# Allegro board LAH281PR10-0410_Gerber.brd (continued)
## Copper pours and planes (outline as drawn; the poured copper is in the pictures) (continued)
LX_IO on TOP (solid shape): 305.96,62.68 305.96,60.42 307.81,58.58 309.83,58.58 309.9,58.5 309.9,58.37 309.82,58.3 308.65,58.3 308.65,58.29 307.5,58.29 307.37,58.16 307.37,56.29 306.2,55.13 306.2,53.84 305.99,53.63 304.54,53.63 304.39,53.77 304.39,62.23 304.87,62.71 305.93,62.71
MODE_IO on TOP (solid shape): 307.62,61.65 307.62,59.98 308.42,59.18 309.01,59.18 309.07,59.12 309.07,58.8 309.04,58.78 307.88,58.78 306.74,59.91 306.74,61.62 306.86,61.74 307.53,61.74
Net_461 on BOTTOM (solid shape): 147.69,141.3 137.69,141.3 137.69,156.3 147.69,156.3
Net_961 on BOTTOM (solid shape): outline of 196 points within 276.35,88.09 280.85,92.59
Net_962 on BOTTOM (solid shape): outline of 193 points within 261.35,88.09 265.85,92.55
Net_963 on BOTTOM (solid shape): outline of 191 points within 246.35,88.09 250.85,92.54
Net_964 on BOTTOM (solid shape): outline of 196 points within 231.35,88.09 235.85,92.59
PGOOD_5V on BOTTOM (solid shape): 55.42,7.21 55.45,7.21 55.92,6.75 56.31,6.75 56.42,6.64 56.42,5.36 56.3,5.24 55.89,5.24 55.62,5.51 55.62,6.46 55.03,7.05 54.16,7.05 54.12,7.09 54.12,7.28 54.17,7.33 55.3,7.33
REG_OUT on BOTTOM (solid shape): 14.53,22.54 14.53,20.97 15.81,19.69 15.81,18.69 15.74,18.62 15.01,18.62 12.67,20.96 12.67,22.72 12.93,22.98 14.09,22.98
RING2 on TOP (solid shape): 388.31,23.13 388.31,22.75 388.06,22.49 386.41,22.49 386.26,22.65 385.29,22.65 385.24,22.7 384.38,22.7 384.33,22.75 384.33,22.9 384.35,22.93 385.34,22.93 385.42,22.85 386.08,22.85 386.48,23.26 388.19,23.26
RING2 on BOTTOM (solid shape): 390.78,18.35 390.88,18.35 391.01,18.23 391.01,17.46 390.93,17.39 390.48,17.39 390.4,17.47 390.34,17.47 390.19,17.62 389.41,17.62 389.15,17.87 389.15,18.63 389.51,18.99 390.14,18.99
RING2 on IN1 (solid shape): 389.15,23 389.15,22.34 389.07,22.27 388.26,22.27 387.91,22.62 387.55,22.62 387.5,22.57 387.27,22.57 387.04,22.8 387.04,23.31 387.17,23.43 388.72,23.43
RING2 on IN1 (solid shape): 390.21,19.79 390.16,19.57 390.24,19.38 390.24,18.89 390.42,18.71 390.42,18.25 390.34,18.18 389.18,18.18 388.74,18.61 388.74,19.85 388.87,19.98 390.01,19.98
RING2_R on TOP (solid shape): 394.89,18.67 394.89,18.19 394.74,18.04 393.16,18.04 392.81,17.68 392.81,17.35 392.94,17.22 392.94,17.02 392.39,16.47 391.97,16.47 391.96,16.48 391.91,16.48 391.63,16.76 391.59,16.82 391.54,16.86 390.97,17.43 390.97,17.86 391.23,18.12 391.71,18.12 392.95,19.36 394.21,19.36
RING2_R on BOTTOM (solid shape): 392.94,17.86 392.94,16.96 392.49,16.51 392.1,16.51 391.26,17.35 391.26,17.93 391.32,18 392.8,18
RING2_R on IN1 (solid shape): 395.67,19.89 395.67,19 395.29,18.62 393.13,18.62 392.87,18.87 392.87,19.33 393.81,20.27 395.29,20.27
S3_OVP on BOTTOM (solid shape): 38.97,15.63 38.97,15.46 39.05,15.31 39.29,15.15 39.57,15.21 39.7,15.22 39.77,15.11 39.77,14.52 39.73,14.52 39.73,13.68 39.58,13.52 37.28,13.52 37.06,13.3 37.06,12.89 36.95,12.79 36.24,12.79 36.13,12.9 36.13,13.79 35.75,14.16 35.75,15.38 36,15.63 37.25,15.63 37.25,15.63
S3_OVP on IN1 (solid shape): outline of 457 points within 31.99,9.5 40.26,17.1
S5_OVP on BOTTOM (solid shape): 44.06,15.56 44.78,15.56 45.4,14.95 45.89,14.95 45.97,14.87 45.97,12.92 45.7,12.64 44.4,12.64 44.34,12.71 44.34,13.5 44.1,13.73 42.97,13.73 42.84,13.86 42.84,14.37 43.51,15.03 43.51,15.49 43.19,15.81 41.76,15.81 41.64,15.92 41.64,16.17 41.73,16.26 43.37,16.26
SA_SW on TOP (solid shape): 283.61,68.77 283.61,64.99 283.82,64.78 285.04,64.78 285.09,64.73 285.09,63.97 284.85,63.73 281.16,63.73 279.58,65.32 279.58,66.13 279.65,66.21 280.54,66.21 280.57,66.23 280.57,67.02 280.54,67.05 279.65,67.05 279.6,67.1 279.6,68.6 279.8,68.79 282.73,68.79 282.86,68.93 283.46,68.93
SDVDD1 on TOP (solid shape): 32.14,26.07 32.14,25.14 31.96,24.96 31.88,24.9 31.82,24.83 31.52,24.52 30.76,24.52 30.59,24.7 30.59,25.9 31,26.3 31.9,26.3
SDVDD1 on BOTTOM (solid shape): 17.42,13.37 17.42,11.85 17.59,11.68 17.59,11.01 17.45,10.87 17.2,10.87 17.04,11.03 17.04,11.81 17.16,11.93 17.16,13.33 17.27,13.43 17.36,13.43
SDVDD1 on BOTTOM (solid shape): 31.69,26.85 31.69,24.64 31.56,24.5 31.41,24.5 31.4,24.51 31.28,24.52 31.15,24.51 31.14,24.5 30.77,24.5 30.55,24.72 30.56,24.76 30.55,24.95 30.45,25.11 30.45,26.41 30.6,26.62 30.57,26.87 30.55,26.91 30.66,27.02 31.52,27.02
SDVDD1 on IN4: outline of 81 points within 16.91,10.72 32.86,25.31
SDVDD2 on TOP (solid shape): 13.22,26.96 13.22,25.61 11.93,24.32 10.41,24.32 10.08,24.65 10.08,25.69 10.51,26.12 11.57,26.12 12.1,26.65 12.1,26.81 12.12,26.95 12.11,27.09 12.29,27.26 12.92,27.26
SDVDD2 on BOTTOM (solid shape): 13.52,26.99 13.52,24.38 13.58,24.32 13.58,23.74 13.48,23.64 12.58,23.64 12.31,23.9 12.31,25.58 11.74,26.15 11.74,26.91 11.93,27.09 13.42,27.09
SDVDD2 on BOTTOM (solid shape): 17,13.38 17,11.97 16.91,11.87 16.91,11.16 16.79,11.04 16.44,11.04 16.42,11.06 16.42,11.56 16.41,11.64 16.37,11.71 16.36,11.72 16.35,11.79 16.35,11.93 16.79,12.36 16.79,13.39 16.84,13.44 16.94,13.44
SDVDD2 on IN2 (solid shape): 13.64,23.96 13.65,23.9 13.66,23.86 13.66,22.92 13.26,22.52 12.79,22.52 12.35,22.96 12.35,24.09 12.57,24.31 13.29,24.31
SDVDD2 on IN2 (solid shape): 17.15,12.26 17.15,12.02 17.11,12 16.92,11.72 17.04,11.41 17.06,11.37 17.05,11.32 16.97,11.15 16.99,10.97 17.01,10.93 16.88,10.8 15.95,10.8 15.85,10.85 15.83,10.97 15.79,11.26 15.54,11.43 15.49,11.44 15.49,12.06 15.86,12.43 16.98,12.43
SLEEVE on TOP (solid shape): 386.41,23.72 386.41,23.48 385.93,23 385.49,23 385.42,23.08 384.38,23.08 384.33,23.13 384.33,23.31 384.35,23.33 385.37,23.33 385.47,23.43 385.62,23.43 386.05,23.87 386.26,23.87
SLEEVE on BOTTOM (solid shape): 389.96,16.25 390.84,16.25 390.93,16.15 390.93,15.59 390.83,15.48 388.21,15.48 388.14,15.56 388.14,16.13 388.63,16.63 389.58,16.63
SLEEVE on IN2 (solid shape): 389.71,16.86 389.71,15.74 389.56,15.59 388.21,15.59 388.16,15.64 388.16,16.55 388.85,17.24 389.33,17.24
SLEEVE on IN2 (solid shape): 387.02,24.09 387.02,23.41 386.53,22.93 385.47,22.93 385.26,23.13 385.26,23.76 385.65,24.14 385.8,24.14 385.93,24.27 386.84,24.27
SLEEVE_R on TOP (solid shape): 391.92,16.27 392.19,16.27 392.69,15.76 394.33,15.76 394.52,15.57 394.52,15.15 394.24,14.87 391.53,14.87 390.52,15.88 390.52,16.82 390.62,16.93 390.62,17 390.73,17.1 391.09,17.1
SLEEVE_R on BOTTOM (solid shape): 392,16.39 392.76,16.39 392.9,16.25 392.9,15.69 392.8,15.59 391.23,15.59 391.12,15.7 391.12,16.14 390.56,16.7 390.56,16.86 390.62,16.93 390.62,17.06 390.71,17.15 391.23,17.15
SLEEVE_R on IN1 (solid shape): 395.81,16.14 395.81,15.38 395.64,15.21 395.09,15.3 395.12,14.75 393.65,14.75 393.39,15 393.39,16.14 393.65,16.4 395.55,16.4
SNUB_1.2V on TOP (solid shape): 132.61,8.3 133.02,8.3 133.3,8.01 133.3,6.25 132.97,5.93 131.58,5.93 131.28,6.23 131.28,8.34 131.51,8.57 132.33,8.57
SNUB_1V on TOP (solid shape): 111.06,40.08 111.85,40.08 112.04,39.89 112.04,38.8 111.81,38.57 110.05,38.57 109.94,38.68 109.9,38.76 109.84,38.83 109.55,38.94 109.28,38.77 109.07,38.98 109.07,40.25 109.17,40.35 110.79,40.35
SNUB_CHG on TOP (solid shape): 97.31,3.17 97.31,1.57 97.07,1.33 95.35,1.33 95.12,1.55 95.12,3.19 95.32,3.38 97.1,3.38
SNUB_IO on TOP (solid shape): 303.35,62.7 303.35,61.08 303.22,60.95 302.23,60.95 301.9,61.28 301.19,61.28 301.14,61.33 301.14,62.32 301.57,62.75 303.3,62.75
SUNB_3VR on TOP (solid shape): 330.38,11.95 331.29,11.95 331.54,11.7 331.54,10.68 331.16,10.3 329.51,10.3 329.26,10.56 329.26,11.95 329.38,12.08 330.25,12.08
UG_1.2V on TOP (solid shape): 124.99,3.34 124.99,1.38 124.74,1.13 123.91,1.13 123.64,1.4 123.64,3.16 123.92,3.44 124.88,3.44
UG_1.2V on TOP (solid shape): 116.25,12.84 116.25,12.18 116.15,12.08 115.49,12.08 115.39,12.18 115.39,12.51 115.24,12.66 114.32,12.66 114.27,12.71 114.27,12.87 114.35,12.94 115.64,12.94 115.75,13.05 116.05,13.05
UG_1.2V on IN1 (solid shape): 117.45,12.59 117.45,11.85 117.42,11.83 115.77,11.83 115.42,12.18 115.42,12.54 115.9,13.02 117.02,13.02
UG_1.2V on IN1 (solid shape): 125.6,3.04 125.6,1.22 125.36,0.97 122.72,0.97 122.65,1.05 122.86,1.39 122.62,1.71 122.57,1.76 122.55,1.77 122.55,3.02 122.86,3.32 125.32,3.32
UG_+1VSP on TOP (solid shape): 102.13,42.88 102.13,41.84 102,41.71 99.99,41.71 99.78,41.92 99.78,42.97 99.87,43.06 101.95,43.06
UG_+1VSP on TOP (solid shape): 106.27,32.59 106.27,32.44 106.3,32.41 106.3,32.4 106.46,32.24 106.52,32.16 106.6,32.1 106.86,31.85 106.86,30.87 106.77,30.79 106.49,30.79 106.43,30.86 106.43,30.94 106.43,31.49 106.39,31.65 106.26,31.74 106.25,31.75 105.74,32.25 105.74,32.56 105.82,32.64 106.22,32.64
UG_+1VSP on IN3 (solid shape): 101.23,43.13 101.23,41.66 101.06,41.5 100.27,41.5 100.01,41.75 100.01,43.08 100.11,43.18 101.17,43.18
UG_+1VSP on IN3 (solid shape): 106.3,32.63 106.3,32.36 106.71,31.95 106.71,31.85 106.58,31.71 105.73,31.71 105.14,32.3 105.14,33.01 105.23,33.1 105.83,33.1
UGATE_CHG on TOP (solid shape): 94.38,10.67 94.38,9.81 94.2,9.64 93,9.64 92.69,9.95 92.69,10.78 92.86,10.95 93.07,10.95 93.09,10.96 94.08,10.96
N17828613 on TOP (solid shape): 51.14,28.35 51.88,28.35 52.31,27.92 52.31,27.05 52.16,26.9 50.73,26.9 50.57,26.74 50.57,26.02 50.49,25.95 49.91,25.95 49.81,26.05 49.81,27.02 49.16,27.67 47.43,27.67 47.08,28.01 47.08,28.49 47.3,28.71 49.84,28.71 50.07,28.94 50.55,28.94
N17829900 on TOP (solid shape): 51.26,32.19 51.26,31.41 51.48,31.19 51.59,30.98 51.79,30.88 51.9,30.77 51.9,29.52 51.7,29.32 51.1,29.32 50.64,29.78 50.64,30.75 49.81,31.58 49.81,32.22 49.92,32.34 51.12,32.34
N17880182 on TOP (solid shape): 58.24,29.33 58.24,28.63 58.27,28.61 58.27,28.44 58.6,28.11 60.44,28.11 60.5,27.94 60.64,27.83 60.68,27.82 60.68,26.56 60.32,26.2 58.65,26.2 58.61,26.21 57.35,27.47 57.35,27.5 57.33,27.53 57.33,27.73 57.25,27.8 57.07,27.8 56.94,27.93 56.94,28.54 56.82,28.67 56.18,28.67 56.1,28.74 56.1,29.34 56.08,29.37 56.08,29.38 56.26,29.56 58.01,29.56
N20816750 on TOP (solid shape): 292.56,16.76 292.56,16.07 292.29,15.81 291.09,15.81 291.08,15.82 290.91,15.87 290.74,15.82 290.73,15.82 290.67,15.82 290.6,15.74 289.76,15.74 289.68,15.82 289.68,15.99 289.81,16.12 290.4,16.12 290.6,16.32 291.07,16.32 291.69,16.94 292.38,16.94
N20816752 on TOP (solid shape): 292.56,18.14 292.56,17.29 292.4,17.13 291.58,17.13 291.13,16.68 290.32,16.68 290.26,16.69 289.85,16.69 289.82,16.69 289.77,16.68 289.66,16.8 289.66,16.98 289.79,17.11 290.93,17.11 291.56,17.74 291.56,18.13 291.7,18.26 292.44,18.26
N20816821 on TOP (solid shape): 290.21,69.93 290.21,69.08 290.05,68.92 289.31,68.92 289.16,68.77 289.16,68.47 288.66,67.96 287.78,67.96 287.72,68.03 287.72,68.24 287.82,68.33 288.59,68.33 288.86,68.6 288.86,69.61 289.27,70.03 290.12,70.03
N20816822 on TOP (solid shape): 290.25,68.6 290.25,67.85 290.06,67.66 289.35,67.66 288.78,67.09 288.74,67.09 288.62,67.09 288.47,66.94 287.8,66.94 287.7,67.03 287.7,67.27 287.82,67.38 287.89,67.37 287.92,67.36 288.33,67.36 288.41,67.38 288.48,67.41 288.5,67.42 288.54,67.42 289.35,68.24 289.35,68.63 289.45,68.73 290.12,68.73
N24451540 on TOP (solid shape): 55.98,29.25 55.98,28.67 55.75,28.44 55.58,28.44 55.56,28.42 55.51,28.42 55.27,28.19 54.81,28.19 54.52,27.91 54.52,27.88 54.52,27.86 54.49,27.72 54.52,27.58 54.52,27.57 54.52,27.54 54.74,27.32 55.32,27.32 55.57,27.57 57.1,27.57 57.22,27.45 57.22,26.94 57.1,26.81 54.66,26.81 54.57,26.85 54.54,26.94 54.45,27.18 54.22,27.3 54.14,27.35 54.11,27.43 54.11,28.06 54.15,28.15 54.25,28.18 54.55,28.31 54.62,28.63 54.65,28.73 54.75,28.78 54.93,28.78 55.16,29.02 55.16,29.21 55.22,29.26 55.96,29.26
N24455122 on TOP (solid shape): 55.95,31 55.95,29.64 55.94,29.63 55.22,29.63 54.94,29.35 54.94,29.1 54.81,28.97 54.43,28.97 54.3,29.1 54.3,30.62 54.56,30.88 54.94,30.88 55.19,31.13 55.83,31.13
N24481164 on BOTTOM (solid shape): 71.17,28.35 71.17,27.33 71.02,27.19 70.35,27.19 70.24,27.08 69.73,27.08 69.56,27.25 69.56,28.48 69.59,28.52 71,28.52
N24501583 on TOP (solid shape): 80,17.91 80.04,17.91 80.21,17.91 80.25,17.91 80.29,17.92 80.46,17.92 80.59,17.79 80.59,16.91 80.34,16.65 79.83,16.65 79.58,16.91 79.58,17.16 79.45,17.29 78.69,17.29 78.56,17.41 78.56,17.79 78.69,17.92 79.96,17.92
N24501661 on TOP (solid shape): 83.89,21.1 83.89,19.83 83.77,19.7 81.1,19.7 80.97,19.83 80.97,20.49 81.02,20.5 81.23,20.67 81.27,20.94 81.29,21.05 81.39,21.1 82.95,21.1
N24501681 on TOP (solid shape): 84.02,19.32 84.02,18.48 83.51,17.97 83.14,17.97 83.09,18.02 83.09,18.03 82.8,18.23 82.48,18.09 82.46,18.06 82.44,18.05 81.48,18.05 81.23,18.3 81.23,19.32 81.35,19.45 83.89,19.45
N24501694 on TOP (solid shape): 89.81,27.36 89.81,25.94 88.51,24.64 88.51,24.28 88.21,23.97 88.21,23.25 87.8,22.84 86.94,22.84 86.69,23.09 86.69,24.19 87.07,24.57 87.07,24.98 87.59,25.5 87.59,25.95 88.15,26.51 88.15,27 88.64,27.49 89.68,27.49
N24501736 on TOP (solid shape): 90.3,22.83 91.42,22.83 91.65,22.6 91.65,21.4 91.46,21.21 90.68,21.21 90.24,21.65 88.86,21.65 88.67,21.85 88.67,22.51 89.15,22.99 90.15,22.99
N24501930 on TOP (solid shape): 84.78,20.54 84.91,20.41 84.91,20.21 85.16,19.95 85.16,19.57 85.04,19.45 84.15,19.45 84.02,19.57 84.02,20.35 84.02,20.97 84.15,21.1 84.78,21.1
N24501932 on TOP (solid shape): 84.91,22.87 84.91,22.37 85.16,22.11 85.54,22.11 85.8,21.86 85.8,20.46 85.67,20.33 85.16,20.33 84.96,20.54 84.96,21.37 84.86,21.47 84.29,21.47 84.2,21.55 84.2,22.16 84.4,22.37 84.4,22.87 84.52,22.99 84.79,22.99
N24565509 on BOTTOM (solid shape): 41.73,19.94 41.73,19.45 41.85,19.33 41.9,19.27 41.95,19.22 42.24,18.94 42.24,18.25 42.43,18.07 44.01,18.07 44.43,18.49 44.43,19.06 44.62,19.25 46.55,19.25 46.82,18.98 46.82,18.52 46.68,18.38 45.32,18.38 44.86,17.92 44.86,16.6 44.7,16.45 44.12,16.45 43.49,17.08 41.68,17.08 41.2,17.56 41.2,19.59 41.2,19.6 41.22,19.73 41.2,19.85 41.19,19.89 41.33,20.03 41.65,20.03
N24565597 on BOTTOM (solid shape): 42.8,22.97 42.8,22.3 42.41,21.91 42.41,21.36 42.33,21.28 42.02,21.28 41.88,21.41 41.88,21.78 41.73,21.94 41.7,21.96 41.25,22.42 41.25,22.82 41.34,22.91 41.91,22.91 42.05,23.05 42.72,23.05
N24623814 on BOTTOM (solid shape): 37.79,19.88 37.79,19.09 37.91,18.98 37.91,18.35 37.17,17.62 37.17,17.17 37.38,16.96 38.82,16.96 38.97,16.82 38.97,16.57 38.85,16.45 35.95,16.45 35.27,17.13 34.54,17.13 34.44,17.23 34.44,17.67 34.56,17.79 34.69,17.79 34.7,17.79 34.99,17.79 35.06,17.87 35.26,17.87 35.27,17.86 35.43,17.86 36.02,18.46 36.02,19.8 36.12,19.9 36.64,19.9 36.78,20.03 37.64,20.03
N24623894 on BOTTOM (solid shape): 38.76,23.18 38.76,22.49 38.43,22.17 38.43,21.96 38.42,21.94 38.42,21.42 38.28,21.28 38.08,21.28 37.94,21.42 37.94,21.84 37.79,21.99 37.83,22.03 37.87,22.48 37.45,22.61 37.33,22.62 37.27,22.73 37.27,23.31 37.35,23.38 38.55,23.38
N25196480 on TOP (solid shape): 357.58,47.26 357.58,46.37 357.5,46.3 356.07,46.3 356.07,46.31 355.23,46.31 355.04,46.5 355.04,47 355.42,47.39 357.45,47.39
N26820574 on TOP (solid shape): 79.24,27.82 79.47,27.73 79.71,27.82 80.61,27.82 80.72,27.7 80.72,27.7 80.97,27.45 80.97,26.05 80.08,25.16 80.08,24.27 78.81,24.27 78.43,24.65 78.43,26.41 78.74,26.71 78.74,27.11 78.58,27.27 78.58,27.67 78.73,27.82
N26822393 on TOP (solid shape): 76.21,24.67 76.21,24.08 76.35,24.08 76.35,22.67 76.15,22.47 75.49,22.47 75.33,22.62 75.33,24.6 75.49,24.75 76.12,24.75
N42077965 on TOP (solid shape): 292.36,60.18 292.36,59.22 292.14,59 291.51,59 291.43,58.92 291.37,58.92 291.37,58.86 290.44,57.93 289.61,57.93 289.55,57.98 289.55,58.23 289.67,58.35 290.38,58.35 290.4,58.36 290.65,58.61 290.65,58.62 291.24,59.21 291.24,60.1 291.44,60.31 292.22,60.31
N42077969 on TOP (solid shape): 292.24,58.74 292.24,57.93 292.16,57.85 291.37,57.85 290.87,57.34 290.84,57.34 290.63,57.24 290.52,57.02 290.52,57 290.43,56.91 290.21,56.91 290.15,56.92 289.75,56.92 289.69,56.91 289.66,56.91 289.57,57 289.57,57.26 289.63,57.33 290.16,57.33 290.2,57.36 290.21,57.36 290.39,57.48 290.43,57.7 290.42,57.73 290.54,57.85 290.54,57.85 291.53,58.84 292.14,58.84
N42078041 on TOP (solid shape): 292.45,49.08 292.45,48.18 292.25,47.97 291.43,47.97 290.69,47.23 289.73,47.23 289.69,47.28 289.69,47.51 289.76,47.59 290.45,47.59 290.47,47.61 290.64,47.61 291.58,48.56 291.58,48.96 291.75,49.12 292.41,49.12
N42078055 on TOP (solid shape): 292.51,47.66 292.51,46.97 292.22,46.68 291.18,46.68 290.72,46.22 290.69,46.19 290.66,46.17 289.85,46.17 289.79,46.17 289.77,46.17 289.66,46.27 289.69,46.29 289.69,46.53 289.78,46.62 289.85,46.61 290.26,46.61 290.32,46.62 290.38,46.64 290.4,46.65 290.46,46.65 291.58,47.77 292.4,47.77
N50626329 on BOTTOM (solid shape): 43.47,32.37 43.47,31 42.86,30.39 42.82,30.39 42.82,30.35 42.75,30.29 42.75,29.76 42.65,29.66 42.4,29.66 42.35,29.6 41.23,29.6 41.09,29.73 41.09,30.37 42.07,31.34 42.07,31.92 42.7,32.55 43.29,32.55
N51087711 on TOP (solid shape): 323.8,2.43 323.8,1.67 323.67,1.54 323.16,1.54 323.15,1.54 323.07,1.55 323,1.54 322.99,1.54 322.27,1.54 322.19,1.63 322.32,1.76 322.32,2.55 323.67,2.55
N51093717 on BOTTOM (solid shape): 51.98,7.29 51.98,6.75 50.36,5.13 50.36,4.18 50.19,4 49.26,4 48.63,4.64 48.63,5.29 50.7,7.36 51.91,7.36
N51093813 on TOP (solid shape): 135.5,111.29 135.5,110.52 135.42,110.44 134.88,110.44 134.4,109.95 134.4,109.52 134.4,109.51 134.4,108.91 134.29,108.81 132.57,108.81 132.4,108.98 132.4,110.85 132.51,110.96 134.67,110.96 134.78,111.07 134.78,111.31 134.85,111.38 135.41,111.38
N61688512 on TOP (solid shape): 106.95,34.82 106.95,34.17 106.91,34.13 104.58,34.13 104.51,34.2 104.51,34.84 104.53,34.86 106.91,34.86
N61692023 on TOP (solid shape): 292.26,28.05 292.26,27.26 292.04,27.04 291.45,27.04 291.35,26.94 291.32,26.91 291.32,26.83 290.86,26.38 290.5,26.38 290.46,26.42 289.7,26.42 289.59,26.52 289.59,26.72 289.69,26.81 290.7,26.81 290.73,26.83 290.74,26.83 290.79,26.89 290.86,26.89 290.87,26.91 290.89,26.91 291,26.99 291.08,27.11 291.09,27.12 291.2,27.23 291.2,27.81 291.49,28.11 292.21,28.11
N61692025 on TOP (solid shape): 292.16,26.8 292.16,25.93 292.08,25.85 291.49,25.85 291.36,25.72 291.34,25.72 291.34,25.71 291.12,25.48 290.9,25.51 290.7,25.4 289.73,25.4 289.64,25.49 289.64,25.72 289.73,25.81 290.48,25.81 291.54,26.86 292.09,26.86
N61692600 on TOP (solid shape): 292.41,38.01 292.41,37.24 292.19,37.03 291.09,37.03 290.52,36.46 289.76,36.46 289.69,36.52 289.71,36.54 289.71,36.83 289.78,36.89 289.85,36.88 290.26,36.88 290.39,36.92 290.5,37.02 290.5,37.03 291.58,38.11 292.31,38.11
N61692604 on TOP (solid shape): 292.53,39.15 292.53,38.56 292.25,38.28 291.35,38.28 290.55,37.47 290.42,37.47 290.4,37.46 289.72,37.46 289.71,37.47 289.71,37.76 289.79,37.84 290.47,37.84 291.23,38.6 291.23,39.26 291.32,39.35 292.33,39.35
N63206214 on BOTTOM (solid shape): 29.36,15 29.36,13.28 29.22,13.15 27.46,13.15 27.27,13.34 27.27,14.58 27.75,15.06 29.3,15.06
N63206214 on BOTTOM (solid shape): 11.2,20.06 11.2,19.13 9.07,17 9.07,15.89 8.84,15.66 8.18,15.66 7.82,16.02 7.82,18.07 9.98,20.23 11.02,20.23
N63206214 on IN3 (solid shape): outline of 824 points within 8.3,5.21 28.7,18.17
N63282645 on TOP (solid shape): 395.86,22.04 395.86,21.5 395.58,21.22 394.4,21.22 394.39,21.24 393.15,21.24 393.14,21.22 393.09,21.22 392.9,21.03 392.43,21.03 392.41,21.02 390.28,21.02 390.05,21.25 390.05,21.95 390.23,22.13 392.63,22.13 393.02,22.52 395.37,22.52
N63282645 on BOTTOM (solid shape): 391.83,22.21 391.96,22.18 392.09,22.19 392.24,22.04 392.24,21.48 392.14,21.38 391.12,21.38 390.74,21 390.38,21 390.29,21.08 390.29,21.97 390.54,22.21
N63361207 on TOP (solid shape): 47.42,19.92 47.42,17.64 47.37,17.54 47.25,17.52 46.88,17.55 46.68,17.23 46.69,17.14 46.73,17.05 46.68,17.02 46.62,17 46.6,17 46.46,16.98 46.33,16.92 46.31,16.91 46.13,16.91 46.03,16.96 46.01,17.06 45.8,17.48 45.36,17.34 43.76,17.34 43.76,17.77 43.4,18.14 43.32,18.14 43.28,18.18 43.28,19.08 43.29,19.09 44.48,19.09 45.2,19.81 45.3,19.81 45.56,19.73 45.81,19.85 45.91,19.89 46,19.84 46.28,19.7 46.57,19.81 46.84,20.08 47.25,20.08

Small or netless copper shapes (teardrops, artwork), in the pictures only: 61 on TOP, 186 on BOTTOM, 3 on IN1, 1 on IN3

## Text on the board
Ref Des/Silkscreen Bottom: H21 | H22 | PWB P/N: | COPYRIGHT 2019 | REV: A00 | ALL RIGHT RESERVED | H13 | JDGFF1 | JDGFF2 | H7 | JDGFF3 | JDGFF4
User.Comments: CR_111_1 | LA-H281P | 2020-04-10 | 2019-04-10 | EDA70 | Voilin
Ref Des/Silkscreen Top: H5 | H9 | H3 | H15 | H11 | H1 | H14
GND4: GND4
GND5: GND5
DEVICE_TYPE_TOP: L7 | L8 | L9 | L10 | L11 | L12 | TOP | GND1 | IN1 | IN2 | GND3 | VCC | GND4 | GND2 | IN3 | IN4 | GND5 | BOT
User.38: L11-GND5 | L9-GND4 | L1-TOP | L2-GND1 | L3-IN1 | L4-GND2 | L5-IN2 | L6-GND3 | L7-VCC | L8-IN3 | L10-IN4 | L12-BOT | 7.4mil | 8.3mil | 6.6mil | 6mil | 5.5mil | 4.5mil | 3.2mil | 4mil | 4.3mil | 5.2/3.5 | 5.5/4 | 6/5 | 4.7/4 | 4/3.4 | 4.3/4.2 | 3.7/4 | 4/3.5 | 4.3/5.2 | 4/4 | 4.3/6 | 3.5/4.5 | 4/4.5 | 3.2/18 | 4.3/16 | 4/18 | 9/3.5 | 3.4mil | L12_1_45mm(Hoz 1oz 2oz)(Top G-V IN1 G-V  IN2 G-V G-V IN3 G-V IN4 G-V Bot)_180820 | LAYER | NAME | STACKUP: 12 LAYER | 35 ohm | 40 ohm | THICKNESS=1.45mm | 42 ohm | 50 ohm | 75 ohm | se 42 | se 50 | 85 ohm | se 52 | 88 ohm | 90 ohm | 100 ohm | L9/L11 | L4/L6 | L2/L4 | L7/L9 | L2 | Ref | L11 | L3 | L10 | L6/L9
User.39: FIGURE | SIZE | 8.0 | 20.0 | 31.0 | 35.0 | 39.0 | 98.0 | 110.0 | 126.0 | 146.0 | 43.0 | 47.0 | 63.0 | 79.0 | 106.0 | 31.0x28.0 | 47.0x26.0 | 51.0x28.0 | 55.0x24.0 | 59.0x24.0 | 63.0x28.0 | 67.0x31.0 | 69.0x20.0 | 75.0x28.0 | 79.0x28.0 | 91.0x31.0 | 94.0x20.0 | 94.0x28.0 | 33.0x31.0 | 110.0x79.0 | DRILL CHART: TOP to BOTTOM | ALL UNITS ARE IN MILS | TOLERANCE | +3.0/-3.0 | +2.0/-2.0 | PLATED | NON-PLATED | QTY | 9085 | 33 | 27 | 10 | 5 | 3 | 9 | 4 | 1 | 12 | 2 | 6
User.40: stack-up setting ok
